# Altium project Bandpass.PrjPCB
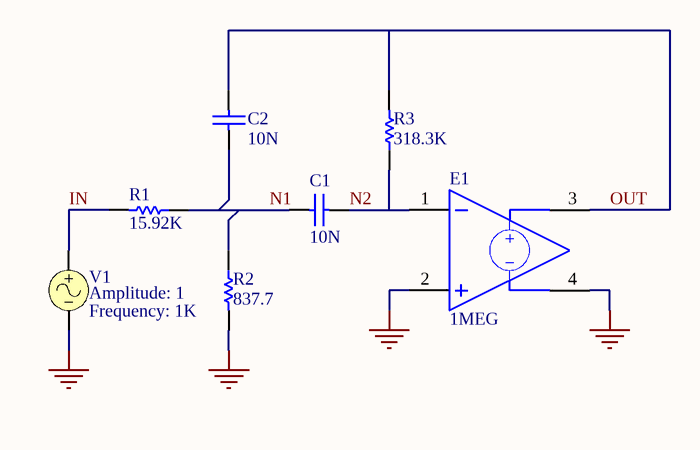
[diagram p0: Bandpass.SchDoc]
1 sheet, 7 parts. Net scope: global (net labels, ports and power ports of the same name join across sheets).

## Sheet Bandpass.SchDoc
size A4; Organization: Altium Limited; Address1: L3, 12a Rodborough Rd; Address2: Frenchs Forest; Address3: NSW; Address4: Australia 2086; DocumentNumber: 1; SheetNumber: 1; SheetTotal: 1

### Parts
C1  10N  [RAD-0.3]
C2  10N  [RAD-0.3]
E1  1MEG
R1  15.92K  [AXIAL-0.3]
R2  837.7  [AXIAL-0.3]
R3  318.3K  [AXIAL-0.3]
V1  Amplitude: 1  Frequency: 1K  (hidden comment: VSIN)

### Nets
GND: E1.2(+IN) E1.4(OUT-) R2.2 V1.2
IN: R1.2 V1.1
N1: C1.1 C2.1 R1.1 R2.1
N2: C1.2 E1.1(-IN) R3.1
OUT: C2.2 E1.3(OUT+) R3.2

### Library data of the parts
C1 C2 = Cap: Capacitor; Manufacturer: Generic Components; Class I: Passive
E1 = VCVS
R1-R3 = Res1: Resistor; Manufacturer: Generic Components; Class I: Passive
V1 = VSIN: Sinusoidal Voltage Source; Manufacturer: Generic Components; Revision 1: 15-Jun-2001: Default value added for damping factor (F8:0).; Revision 2: 17-July-2002: Re-released for DXP Platform.; Class I: Simulation; Note: PCB Footprint - Not required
